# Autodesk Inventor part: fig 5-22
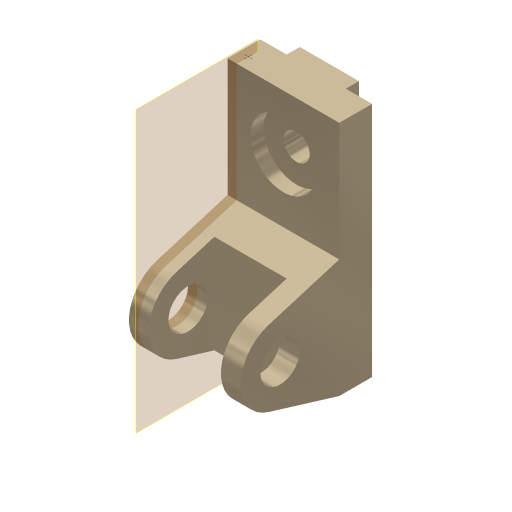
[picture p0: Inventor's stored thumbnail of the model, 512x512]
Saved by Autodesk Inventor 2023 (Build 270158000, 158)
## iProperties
Created: 2001-11
Part Number: fig 5-22
Document SubType Name: Modeling
Designer: Renu Muthoo
Density: 1 g/cm^3
Material: Generic
Appearance: Metal-Titanium (Polished)
Control State: 0
Master: False
Checked Out: False
Shininess: 65.0
Angle Display Precision: 2
Document Length Units: 11269
Document Angle Units: 11279
Document Time Units: 11290
Document Mass Units: 11283
Document Length Units Precision: 3
Document Angle Units Precision: 2
Compacted: False
Density: 0.0
Volumn: 0.0
Area: 0.0
PropertySet Name: Model Information
Author: Renu Muthoo
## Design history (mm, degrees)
node "Sketch1"
sketch "Sketch2"
  geometry: L1 (33.257, 104.664)-(33.257, -75.336); L2 (33.257, -75.336)-(8.257, -75.336); L3 (8.257, -75.336)-(-45.451, -59.045); L4 (-45.451, -1.628)-(8.257, 14.664); L5 (8.257, 14.664)-(8.257, 104.664); L6 (8.257, 104.664)-(33.257, 104.664); C1 r 15 at (-36.743, -30.336); A1 r 30 centre (-36.743, -30.336) between (-45.451, -1.628) and (-45.451, -59.045)
  constraints: 12 end point, 2 centre point, 2 equal length, 2 parallel, 2 point on circle, 2 tangent, 1 coincident, 1 perpendicular, 1 vertical
  dimensions: "d0" = 180 distance of L1.start L1.end; "d1" = 30 radius of A1; "d2" = 25 distance of L5.end L1.start; "d3" = 45 distance from line of L2 A1.centre; "d4" = 70 distance from line of L1 A1.centre; "d5" = 30 diameter of C1
extrude "Extrusion1" new body sketch "Sketch2" distance "d6" = 85; taper "d7" = 0 deg
workplane "Work Plane1"
sketch "Sketch3"
  geometry: L1 (15, 62.364)-(70, 62.364); L2 (70, 62.364)-(70, -52.386); L3 (70, -52.386)-(15, -52.386); L4 (15, -52.386)-(15, 62.364); L5 (0, -45)-(0, -28.708) reference
  constraints: 8 end point, 2 parallel, 1 horizontal, 1 perpendicular
  dimensions: "d8" = 55 distance of L1.start L1.end; "d9" = 15 distance between parallel lines of L5 L4
extrude "Extrusion2" cut sketch "Sketch3" distance "d10" = 50; taper "d11" = 0 deg
sketch "Sketch4"
  geometry: L1 (0, 25)-(85, 25) reference; L2 (0, 0)-(0, 25) reference; L3 (20, 25)-(65, 25); L4 (65, 25)-(65, 35); L5 (65, 35)-(20, 35); L6 (20, 35)-(20, 25)
  constraints: 8 end point, 2 parallel, 1 horizontal, 1 perpendicular, 1 point on line
  dimensions: "d12" = 45 distance of L4.end L5.end; "d13" = 10 distance of L3.end L4.end; "d14" = 20 distance between parallel lines of L2 L6
extrude "Extrusion3" join sketch "Sketch4" stored distance "d15" = 50; taper "d16" = 0 deg
sketch "Sketch5"
  geometry: L1 (85, 0)-(85, 90) reference; L2 (0, 90)-(85, 90) reference; 1 further point
  dimensions: "d17" = 42 distance from line of L2 point (42.5, 48); "d18" = 42.5 distance from line of L1 point (42.5, 48)
hole "Hole1" sketch "Sketch5" at (42.5, 48) diameter "d19" = 20; stored, may be unused: countersink angle "d23" = 82 deg, drill point angle "d25" = 118 deg; dims "d20" = 6, "d21" = 50, "d22" = 10, "d24" = 8
sketch "Sketch11"
  geometry: 1 further point
workplane "Work Plane17"
body "Solid1"
